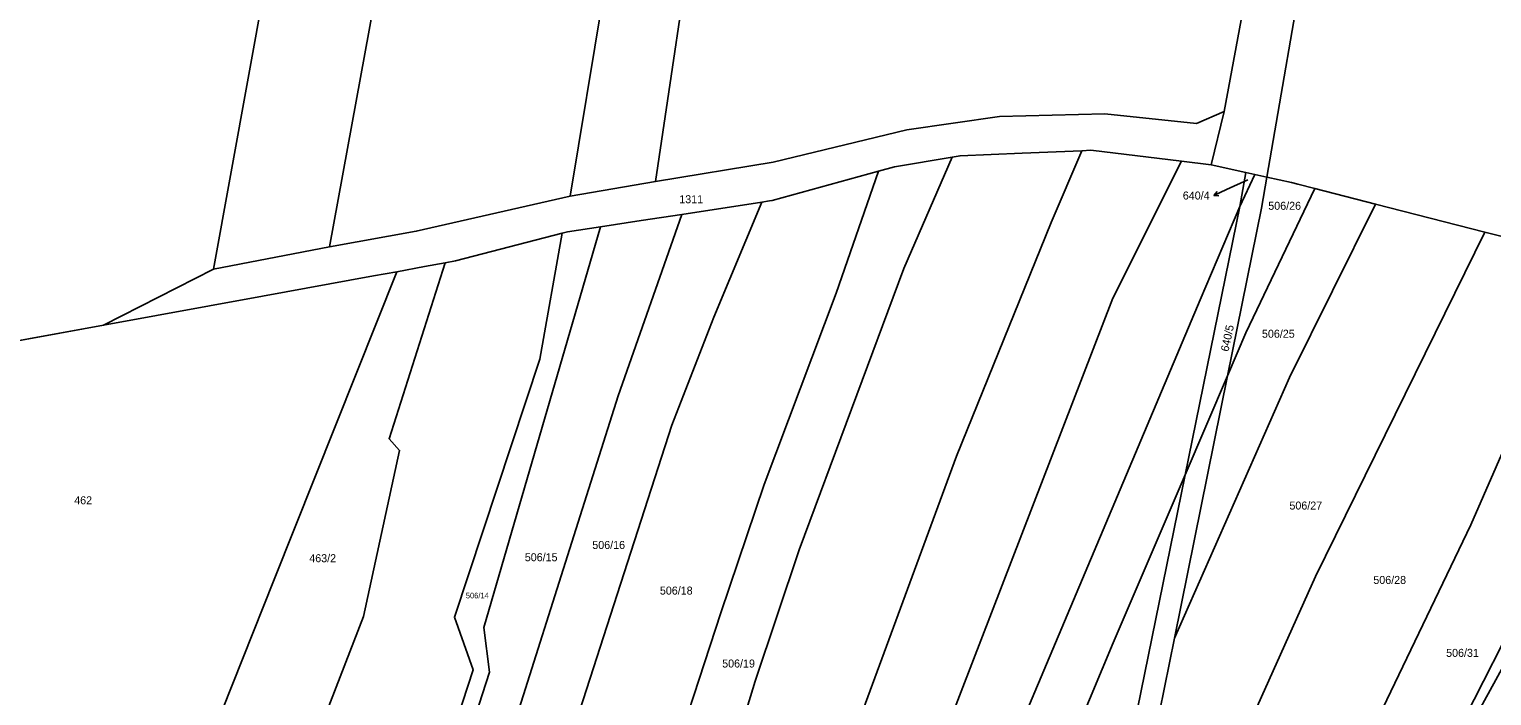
# Model space of a CAD drawing. Extents: x -746176 to -739709, y -1128407 to -1124482.
# Drawn here: x -742784.8 to -742474.2, y -1126883.6 to -1126742.1 of the extents above; entities that cross this region are included whole.
import ezdxf

# ---------------------------------------------------------------- set-up
doc = ezdxf.new("R2010")
doc.units = 0
for name, color, linetype in [('Hranice parcel', 7, 'Continuous'), ('Parcelní čísla', 7, 'Continuous'), ('Pop  PČ popisy', 7, 'Continuous'), ('Vrstva 55', 7, 'Continuous')]:
    doc.layers.add(name, color=color, linetype=linetype)

msp = doc.modelspace()

# ---------------------------------------------------------------- linework, layer by layer
at = {"layer": 'Hranice parcel'}
for p, q in [((-742669.88, -1126777.52), (-742639.25, -1126591.77)), ((-742531.03, -1126759.57), (-742533.77, -1126770.91)), ((-742540.06, -1126770.15), (-742533.77, -1126770.91)), ((-742540.06, -1126770.15), (-742533.77, -1126770.91)), ((-742533.77, -1126770.91), (-742526.41, -1126772.54)), ((-742533.77, -1126770.91), (-742526.41, -1126772.54)), ((-742669.88, -1126777.52), (-742651.76, -1126774.43)), ((-742527.67, -1126779.74), (-742526.41, -1126772.54)), ((-742527.67, -1126779.74), (-742524.54, -1126772.95)), ((-742526.41, -1126772.54), (-742524.54, -1126772.95)), ((-742526.41, -1126772.54), (-742524.54, -1126772.95)), ((-742524.54, -1126772.95), (-742521.95, -1126773.52)), ((-742524.54, -1126772.95), (-742521.95, -1126773.52)), ((-742511.74, -1126775.91), (-742498.85, -1126779.22)), ((-742511.74, -1126775.91), (-742498.85, -1126779.22)), ((-742646.21, -1126781.41), (-742629.18, -1126778.81)), ((-742646.21, -1126781.41), (-742629.18, -1126778.81)), ((-742539.32, -1126836.74), (-742527.67, -1126779.74)), ((-742498.85, -1126779.22), (-742475.66, -1126785.18)), ((-742498.85, -1126779.22), (-742475.66, -1126785.18)), ((-742475.66, -1126785.18), (-742451.42, -1126791.4)), ((-742475.66, -1126785.18), (-742451.42, -1126791.4)), ((-742745.64, -1126793.01), (-742721.02, -1126788.32)), ((-742745.64, -1126793.01), (-742769.01, -1126804.93)), ((-742706.72, -1126793.58), (-742700.87, -1126792.51)), ((-742706.72, -1126793.58), (-742700.87, -1126792.51)), ((-742700.87, -1126792.51), (-742696.43, -1126791.7)), ((-742700.87, -1126792.51), (-742696.43, -1126791.7)), ((-742530.29, -1126815.68), (-742541.56, -1126871.36)), ((-742530.29, -1126815.68), (-742539.32, -1126836.74)), ((-742550.57, -1126891.8), (-742539.32, -1126836.74)), ((-742465.86, -1126866.52), (-742477.38, -1126887.58))]:
    msp.add_line(p, q, dxfattribs=at)
for points in [[(-742521.95, -1126773.52), (-742504.56, -1126672.68), (-742497, -1126628.23), (-742488.98, -1126567.9), (-742478.35, -1126466.13), (-742467.6, -1126363.23), (-742463.32, -1126296.13), (-742459.73, -1126263.65), (-742452.82, -1126263.88), (-742450.23, -1126260.63), (-742452.38, -1126257.65), (-742458.75, -1126256.81), (-742455.22, -1126201.03)], [(-742482.39, -1126414.71), (-742498.43, -1126567.43), (-742506.05, -1126624.82), (-742531.03, -1126759.57)], [(-742684.93, -1126590.96), (-742709.04, -1126591.22), (-742727.32, -1126691.99), (-742745.64, -1126793.01)], [(-742684.93, -1126590.96), (-742703.12, -1126690.44), (-742721.02, -1126788.32)], [(-742651.76, -1126774.43), (-742624.84, -1126593.06), (-742639.25, -1126591.77)], [(-742531.03, -1126759.57), (-742536.88, -1126762.13), (-742556.33, -1126760.06), (-742578.73, -1126760.64), (-742598.4, -1126763.45), (-742626.82, -1126770.34), (-742651.76, -1126774.43)], [(-742561.23, -1126767.89), (-742567.77, -1126783.13), (-742587.89, -1126832.72), (-742634.42, -1126959.12), (-742661.75, -1127022.4)], [(-742588.76, -1126769.25), (-742587.09, -1126768.97), (-742573.9, -1126768.42), (-742561.23, -1126767.89)], [(-742588.76, -1126769.25), (-742587.09, -1126768.97), (-742573.9, -1126768.42), (-742561.23, -1126767.89)], [(-742561.23, -1126767.89), (-742559.37, -1126767.81), (-742540.06, -1126770.15)], [(-742561.23, -1126767.89), (-742559.37, -1126767.81), (-742540.06, -1126770.15)], [(-742679.87, -1127010.3), (-742661.43, -1126968.75), (-742645.29, -1126928.59), (-742630.66, -1126880.5), (-742621.29, -1126852.62), (-742599.04, -1126792.93), (-742588.76, -1126769.25)], [(-742648.95, -1127033.28), (-742621.1, -1126971.78), (-742603.91, -1126926.94), (-742554.63, -1126799.18), (-742540.06, -1126770.15)], [(-742604.44, -1126772.24), (-742601.05, -1126771.3), (-742588.76, -1126769.25)], [(-742604.44, -1126772.24), (-742601.05, -1126771.3), (-742588.76, -1126769.25)], [(-742688.81, -1127002.53), (-742675.39, -1126975.35), (-742650.59, -1126904.79), (-742637.92, -1126865.97), (-742628.71, -1126838.73), (-742613.44, -1126798.13), (-742604.44, -1126772.24)], [(-742629.18, -1126778.81), (-742627.56, -1126778.56), (-742627.03, -1126778.48), (-742604.44, -1126772.24)], [(-742629.18, -1126778.81), (-742627.56, -1126778.56), (-742627.03, -1126778.48), (-742604.44, -1126772.24)], [(-742521.95, -1126773.52), (-742523.09, -1126780.11), (-742530.29, -1126815.68)], [(-742521.95, -1126773.52), (-742516.73, -1126774.67), (-742515.35, -1126774.98), (-742511.74, -1126775.91)], [(-742521.95, -1126773.52), (-742516.73, -1126774.67), (-742515.35, -1126774.98), (-742511.74, -1126775.91)], [(-742721.02, -1126788.32), (-742702.6, -1126784.99), (-742669.88, -1126777.52)], [(-742511.74, -1126775.91), (-742526.39, -1126806.59), (-742530.29, -1126815.68)], [(-742703.1, -1126987.76), (-742688.91, -1126951.77), (-742648.33, -1126826.13), (-742639.39, -1126803.22), (-742629.18, -1126778.81)], [(-742638.43, -1127039.61), (-742614.56, -1126990.57), (-742601.46, -1126960.43), (-742573.73, -1126888.65), (-742536.1, -1126799.53), (-742527.67, -1126779.74)], [(-742541.56, -1126871.36), (-742517.16, -1126816.01), (-742498.85, -1126779.22)], [(-742710.71, -1126977.95), (-742691.49, -1126920.27), (-742659.71, -1126819.94), (-742646.21, -1126781.41)], [(-742663.45, -1126784.04), (-742654.84, -1126782.73), (-742646.21, -1126781.41)], [(-742663.45, -1126784.04), (-742654.84, -1126782.73), (-742646.21, -1126781.41)], [(-742719.6, -1126967.23), (-742690.51, -1126878.08), (-742694.48, -1126866.91), (-742676.36, -1126812.17), (-742671.59, -1126785.41)], [(-742716.17, -1126970.68), (-742712.23, -1126956.56), (-742687.03, -1126878.58), (-742688.27, -1126869.14), (-742663.45, -1126784.04)], [(-742696.43, -1126791.7), (-742694.29, -1126791.31), (-742671.59, -1126785.41)], [(-742696.43, -1126791.7), (-742694.29, -1126791.31), (-742671.59, -1126785.41)], [(-742671.59, -1126785.41), (-742670.45, -1126785.11), (-742665.8, -1126784.4), (-742663.45, -1126784.04)], [(-742671.59, -1126785.41), (-742670.45, -1126785.11), (-742665.8, -1126784.4), (-742663.45, -1126784.04)], [(-742562.72, -1126972.14), (-742511.64, -1126858.28), (-742475.66, -1126785.18)], [(-742730.7, -1126910.48), (-742713.83, -1126866.81), (-742706.14, -1126831.54), (-742708.37, -1126829.06), (-742696.43, -1126791.7)], [(-742576.22, -1127042.62), (-742572.46, -1127037.81), (-742549.96, -1126996.44), (-742502.42, -1126896.85), (-742478.65, -1126847.35), (-742462.47, -1126810.41), (-742451.42, -1126791.4)], [(-742769.01, -1126804.93), (-742735.24, -1126798.77), (-742711.7, -1126794.48), (-742706.72, -1126793.58)], [(-742769.01, -1126804.93), (-742735.24, -1126798.77), (-742711.7, -1126794.48), (-742706.72, -1126793.58)], [(-742750.49, -1126903.46), (-742732.76, -1126858.93), (-742706.72, -1126793.58)], [(-742431.72, -1126796.46), (-742469.95, -1126868.69), (-742501.91, -1126931.51), (-742517.1, -1126960.81), (-742540.36, -1126998.76), (-742553.75, -1127021.53), (-742568.92, -1127039.08), (-742575.31, -1127045.24)], [(-742800.98, -1126810.76), (-742782.52, -1126807.39), (-742769.01, -1126804.93)], [(-742800.98, -1126810.76), (-742782.52, -1126807.39), (-742769.01, -1126804.93)], [(-742629.44, -1127044.36), (-742612.06, -1127010.59), (-742600.55, -1126985.29), (-742577.05, -1126926.06), (-742554.59, -1126872.35), (-742539.32, -1126836.74)], [(-742541.56, -1126871.36), (-742553.22, -1126928.98), (-742562.72, -1126972.14)]]:
    msp.add_lwpolyline(points, dxfattribs=at)
at = {"layer": 'Pop  PČ popisy'}
for p, q in [((-742526.01, -1126774.1), (-742530.52, -1126776.16)), ((-742530.52, -1126776.16), (-742533.24, -1126777.43)), ((-742533.24, -1126777.43), (-742532.54, -1126776.55)), ((-742533.24, -1126777.43), (-742532.12, -1126777.46))]:
    msp.add_line(p, q, dxfattribs=at)
at = {"layer": 'Vrstva 55'}
msp.add_lwpolyline([(-743029.24, -1126857.99), (-743022.12, -1126856.61), (-743014.97, -1126855.23), (-742997.62, -1126851.06), (-742992.38, -1126849.75), (-742987.15, -1126848.45), (-742983.82, -1126847.62), (-742967.54, -1126845.19), (-742949.34, -1126840.52), (-742939.84, -1126838.09), (-742925.21, -1126834.34), (-742909.52, -1126830.92), (-742897.44, -1126829.55), (-742885.68, -1126828.21), (-742883.83, -1126827.8), (-742866.72, -1126824.05), (-742859.97, -1126822.57), (-742849.79, -1126820.34), (-742821.45, -1126814.49), (-742800.98, -1126810.76), (-742769.01, -1126804.93)], dxfattribs=at)

# ---------------------------------------------------------------- texts
at = {"layer": 'Parcelní čísla'}
for s, height, p in [('1311', 1.7, (-742646.74, -1126779.05)), ('640/4', 1.7, (-742539.8, -1126778.26)), ('506/26', 1.7, (-742521.65, -1126780.44)), ('506/25', 1.7, (-742522.99, -1126807.6)), ('462', 1.7, (-742775.24, -1126842.96)), ('506/27', 1.7, (-742517.16, -1126844.08)), ('506/16', 1.7, (-742665.21, -1126852.44)), ('463/2', 1.7, (-742725.32, -1126855.26)), ('506/15', 1.7, (-742679.55, -1126855.05)), ('506/28', 1.7, (-742499.34, -1126859.87)), ('506/18', 1.7, (-742650.86, -1126862.13)), ('506/14', 1.19, (-742692.07, -1126862.93)), ('506/31', 1.7, (-742483.88, -1126875.35)), ('506/19', 1.7, (-742637.63, -1126877.61))]:
    msp.add_text(s, height=height, dxfattribs=at).set_placement(p)
msp.add_text('640/5', height=1.7, rotation=78, dxfattribs=at).set_placement((-742530.11, -1126810.64))

doc.saveas('drawing.dxf')
